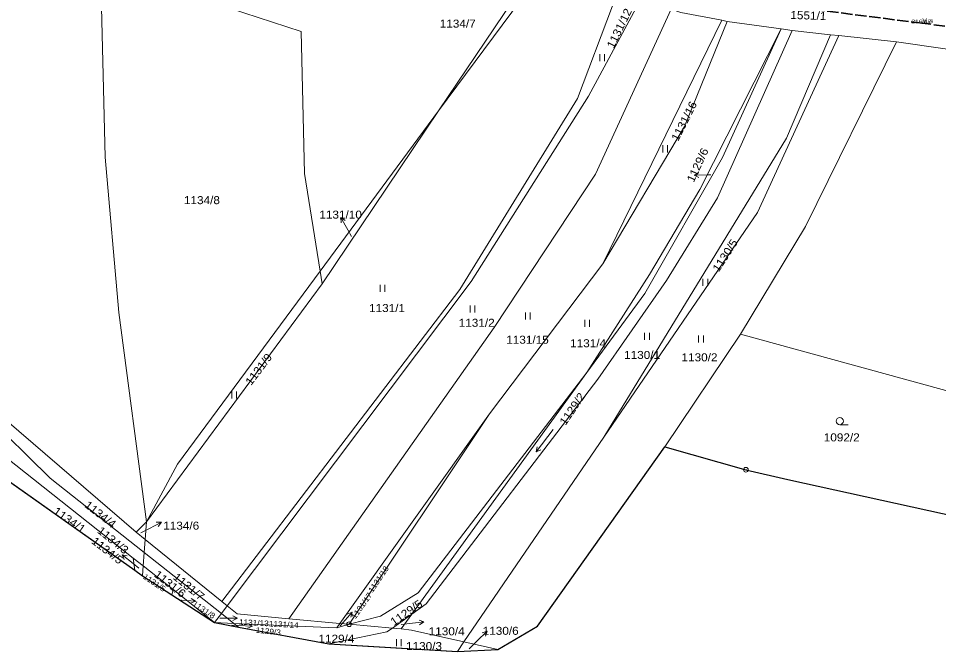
# Model space of a CAD drawing. Extents: x -686207 to -681951, y -1020493 to -1017811.
# Drawn here: x -684516.8 to -684321.3, y -1019707.1 to -1019572.5 of the extents above; entities that cross this region are included whole.
import ezdxf
from ezdxf.enums import TextEntityAlignment as Align

# ---------------------------------------------------------------- set-up
doc = ezdxf.new("R2010")
doc.units = 0
doc.header["$LTSCALE"] = 0.4
doc.header["$PDMODE"] = 32
doc.header["$PDSIZE"] = 0.2
doc.linetypes.add('LONG_DASHED', pattern=[7.5, 6, -1.5])
for name, color, linetype, lineweight in [('1', 7, 'Continuous', 13), ('24', 7, 'Continuous', 25), ('3', 7, 'Continuous', 13), ('35', 7, 'LONG_DASHED', 35), ('4', 7, 'Continuous', 13), ('7', 7, 'Continuous', 13), ('8', 7, 'Continuous', 13)]:
    doc.layers.add(name, color=color, linetype=linetype, lineweight=lineweight)
doc.layers.add('2', color=7, linetype='Continuous')

msp = doc.modelspace()

# ---------------------------------------------------------------- linework, layer by layer
at = {"layer": '1'}
for p, q in [((-684392.65, -1019624.67), (-684367.36, -1019572.95)), ((-684367.36, -1019572.95), (-684366.25, -1019573.17)), ((-684354.74, -1019574.74), (-684352.46, -1019575.08)), ((-684352.46, -1019575.08), (-684344.26, -1019576)), ((-684344.26, -1019576), (-684342.52, -1019576.2)), ((-684342.52, -1019576.2), (-684330.26, -1019577.49)), ((-684427.54, -1019592.19), (-684452.7, -1019626.22)), ((-684427.54, -1019592.19), (-684452.27, -1019628.92)), ((-684452.27, -1019628.92), (-684452.7, -1019626.22)), ((-684452.27, -1019628.92), (-684489.58, -1019679.5)), ((-684363.38, -1019639.61), (-684379.46, -1019663.55)), ((-684363.38, -1019639.61), (-684307.12, -1019655.1)), ((-684396.02, -1019647.8), (-684433.21, -1019699.09)), ((-684422.17, -1019705.03), (-684392.45, -1019661.53)), ((-684492.41, -1019687.22), (-684523.29, -1019662.77)), ((-684406.56, -1019701.65), (-684379.46, -1019663.55)), ((-684522.6, -1019668.21), (-684492.12, -1019689.8)), ((-684489.88, -1019683.27), (-684491.79, -1019681.72)), ((-684489.88, -1019683.27), (-684473.63, -1019696.41)), ((-684490.1, -1019686.01), (-684490.32, -1019688.88)), ((-684473.69, -1019698.98), (-684490.1, -1019686.01)), ((-684492.41, -1019687.22), (-684490.32, -1019688.88)), ((-684492.12, -1019689.8), (-684492.41, -1019687.22)), ((-684490.48, -1019690.96), (-684492.12, -1019689.8)), ((-684490.32, -1019688.88), (-684490.48, -1019690.96)), ((-684483.97, -1019693.9), (-684490.32, -1019688.88)), ((-684484.2, -1019695.03), (-684490.48, -1019690.96)), ((-684484.2, -1019695.03), (-684483.97, -1019693.9)), ((-684484.2, -1019695.03), (-684475.13, -1019700.9)), ((-684471.05, -1019701.07), (-684473.69, -1019698.98)), ((-684470.07, -1019701.85), (-684471.05, -1019701.07)), ((-684449.2, -1019702.01), (-684471.05, -1019701.07)), ((-684470.07, -1019701.85), (-684450.86, -1019705.44)), ((-684448.54, -1019701.08), (-684459.35, -1019700.09)), ((-684449.2, -1019702.01), (-684448.54, -1019701.08)), ((-684446.56, -1019701.26), (-684449.2, -1019702.01)), ((-684446.56, -1019701.26), (-684448.54, -1019701.08)), ((-684437.37, -1019702.07), (-684446.56, -1019701.26)), ((-684450.86, -1019705.44), (-684431.71, -1019706.58)), ((-684422.17, -1019705.03), (-684414.98, -1019706.64))]:
    msp.add_line(p, q, dxfattribs=at)
for points in [[(-684489.58, -1019679.5), (-684495.52, -1019635.01), (-684498.37, -1019602.06), (-684499.38, -1019561.4), (-684456.73, -1019575.36), (-684456.05, -1019605.49), (-684452.7, -1019626.22)], [(-684384.64, -1019568.56), (-684395.73, -1019589.06), (-684420.63, -1019628.47), (-684472.46, -1019697.35)], [(-684410.18, -1019568.72), (-684427.54, -1019592.19), (-684411.67, -1019568.63)], [(-684473.63, -1019696.41), (-684423.04, -1019630.15), (-684398.06, -1019589.57), (-684390.58, -1019569.88)], [(-684459.35, -1019700.09), (-684415.72, -1019638.24), (-684394.21, -1019605.65), (-684378.14, -1019570.61)], [(-684378.14, -1019570.61), (-684376.08, -1019571.26), (-684367.36, -1019572.95)], [(-684366.25, -1019573.17), (-684375.27, -1019595.48), (-684392.65, -1019624.67), (-684416.75, -1019656.53)], [(-684396.02, -1019647.8), (-684382.77, -1019626.93), (-684372.05, -1019608.93), (-684354.74, -1019574.74), (-684366.25, -1019573.17)], [(-684354.74, -1019574.74), (-684367.21, -1019602.1), (-684383.71, -1019630.97), (-684396.02, -1019647.8)], [(-684433.21, -1019699.09), (-684430.19, -1019696.93), (-684393.69, -1019649.17), (-684379.1, -1019628.23), (-684368.3, -1019610.64), (-684352.46, -1019575.08)], [(-684392.45, -1019661.53), (-684353.6, -1019598.02), (-684344.26, -1019576)], [(-684342.52, -1019576.2), (-684359.81, -1019613.76), (-684392.45, -1019661.53)], [(-684330.26, -1019577.49), (-684349.57, -1019616.78), (-684363.38, -1019639.61)], [(-684282.45, -1019625.86), (-684283.23, -1019624.61), (-684283.59, -1019589.07), (-684288.88, -1019583.44), (-684330.26, -1019577.49)], [(-684452.7, -1019626.22), (-684483.04, -1019667.25), (-684489.58, -1019679.5)], [(-684525.18, -1019647.91), (-684519.28, -1019658.03), (-684491.79, -1019681.72)], [(-684446.56, -1019701.26), (-684439.86, -1019699.56), (-684431.9, -1019694.61), (-684396.02, -1019647.8)], [(-684490.1, -1019686.01), (-684510.09, -1019670.21), (-684524.09, -1019656.5)], [(-684448.54, -1019701.08), (-684416.75, -1019656.53), (-684446.56, -1019701.26)], [(-684353.33, -1019670.49), (-684362.26, -1019668.43), (-684379.46, -1019663.55)], [(-684289.75, -1019683.18), (-684291.23, -1019682.83), (-684302.3, -1019681.04), (-684310.5, -1019679.94), (-684353.33, -1019670.49)], [(-684491.79, -1019681.72), (-684489.58, -1019679.5), (-684489.88, -1019683.27), (-684490.1, -1019686.01)], [(-684483.97, -1019693.9), (-684475.13, -1019700.9), (-684470.07, -1019701.85)], [(-684473.69, -1019698.98), (-684472.46, -1019697.35), (-684473.63, -1019696.41)], [(-684472.46, -1019697.35), (-684470.34, -1019699.07), (-684459.35, -1019700.09)], [(-684471.05, -1019701.07), (-684475.13, -1019700.9), (-684473.69, -1019698.98)], [(-684423.56, -1019707.07), (-684414.98, -1019706.64), (-684406.56, -1019701.65)], [(-684450.86, -1019705.44), (-684438.52, -1019702.9), (-684437.37, -1019702.07)], [(-684435.49, -1019702.24), (-684433.32, -1019702.54), (-684422.17, -1019705.03)], [(-684431.71, -1019706.58), (-684423.56, -1019707.07), (-684422.17, -1019705.03)]]:
    msp.add_lwpolyline(points, dxfattribs=at)
msp.add_lwpolyline([(-684435.49, -1019702.24), (-684437.37, -1019702.07), (-684433.21, -1019699.09)], close=True, dxfattribs=at)
msp.add_point((-684324.75, -1019573.56), dxfattribs=at)
at = {"layer": '24'}
msp.add_lwpolyline([(-684500.14, -1019451.56), (-684512.05, -1019478.99), (-684531.89, -1019512.67), (-684532.04, -1019515.06), (-684532.26, -1019518.47), (-684532.49, -1019522.07), (-684532.66, -1019524.82), (-684541.65, -1019550.12), (-684527.53, -1019664.73), (-684522.6, -1019668.21), (-684492.12, -1019689.8), (-684490.48, -1019690.96), (-684484.2, -1019695.03), (-684475.13, -1019700.9), (-684470.07, -1019701.85), (-684450.86, -1019705.44), (-684423.56, -1019707.07), (-684414.98, -1019706.64), (-684406.56, -1019701.65), (-684379.46, -1019663.55), (-684362.26, -1019668.43), (-684353.33, -1019670.49), (-684310.5, -1019679.94)], dxfattribs=at)
at = {"layer": '3'}
for p, q in [((-684393.311, -1019581.63), (-684393.311, -1019580.13)), ((-684392.31, -1019581.63), (-684392.31, -1019580.13)), ((-684379.921, -1019601.01), (-684379.921, -1019599.51)), ((-684378.92, -1019601.01), (-684378.92, -1019599.51)), ((-684439.991, -1019630.63), (-684439.991, -1019629.13)), ((-684438.99, -1019630.63), (-684438.99, -1019629.13)), ((-684371.381, -1019629.36), (-684371.381, -1019627.86)), ((-684370.38, -1019629.36), (-684370.38, -1019627.86)), ((-684420.831, -1019635.01), (-684420.831, -1019633.51)), ((-684419.83, -1019635.01), (-684419.83, -1019633.51)), ((-684409.061, -1019636.53), (-684409.061, -1019635.03)), ((-684408.06, -1019636.53), (-684408.06, -1019635.03)), ((-684396.491, -1019638.1), (-684396.491, -1019636.6)), ((-684395.49, -1019638.1), (-684395.49, -1019636.6)), ((-684383.771, -1019640.84), (-684383.771, -1019639.34)), ((-684382.77, -1019640.84), (-684382.77, -1019639.34)), ((-684372.301, -1019641.42), (-684372.301, -1019639.92)), ((-684371.3, -1019641.42), (-684371.3, -1019639.92)), ((-684471.481, -1019653.33), (-684471.481, -1019651.83)), ((-684470.48, -1019653.33), (-684470.48, -1019651.83)), ((-684342.303, -1019658.86), (-684340.553, -1019658.86)), ((-684406.793, -1019664.664), (-684406.605, -1019663.582)), ((-684436.481, -1019705.9), (-684436.481, -1019704.4)), ((-684435.48, -1019705.9), (-684435.48, -1019704.4))]:
    msp.add_line(p, q, dxfattribs=at)
msp.add_lwpolyline([(-684403.182, -1019659.873), (-684406.793, -1019664.664), (-684405.804, -1019664.186)], dxfattribs=at)
msp.add_circle((-684342.3029, -1019658.1098), 0.75, dxfattribs=at)
at = {"layer": '35'}
msp.add_lwpolyline([(-684314.027, -1019574.999), (-684324.75, -1019573.56), (-684347.24, -1019570.74), (-684348.992, -1019570.517)], dxfattribs=at)
at = {"layer": '7'}
for p, q in [((-684373.249, -1019605.875), (-684372.231, -1019606.34)), ((-684448.295, -1019614.845), (-684448.247, -1019615.964)), ((-684446.07, -1019618.86), (-684446.84, -1019617.47)), ((-684486.45, -1019679.551), (-684487.57, -1019679.579)), ((-684494.805, -1019686.522), (-684494.324, -1019687.534)), ((-684479.19, -1019696.372), (-684480.144, -1019695.785)), ((-684482.18, -1019696.11), (-684482.22, -1019696.11)), ((-684470.269, -1019699.938), (-684471.28, -1019699.454)), ((-684445.912, -1019698.71), (-684446.954, -1019699.119)), ((-684467.123, -1019701.667), (-684468.097, -1019701.115)), ((-684430.655, -1019700.776), (-684431.704, -1019700.383)), ((-684417.231, -1019702.755), (-684418.3, -1019703.091)), ((-684421.05, -1019706.45), (-684419.39, -1019704.84))]:
    msp.add_line(p, q, dxfattribs=at)
for points in [[(-684369.69, -1019605.75), (-684370.25, -1019605.77), (-684373.249, -1019605.875), (-684372.266, -1019605.339)], [(-684446.84, -1019617.47), (-684448.295, -1019614.845), (-684447.371, -1019615.478)], [(-684490.8, -1019681.86), (-684489.1, -1019680.96), (-684486.45, -1019679.551), (-684487.099, -1019680.463)], [(-684491.23, -1019689.33), (-684492.44, -1019688.37), (-684494.805, -1019686.522), (-684493.707, -1019686.744)], [(-684482.18, -1019696.11), (-684479.19, -1019696.372), (-684480.232, -1019696.783)], [(-684448.49, -1019701.57), (-684447.92, -1019700.94), (-684445.912, -1019698.71), (-684446.21, -1019699.789)], [(-684474.01, -1019700), (-684473.27, -1019699.99), (-684470.269, -1019699.938), (-684471.262, -1019700.456)], [(-684471.49, -1019701.43), (-684470.12, -1019701.51), (-684467.123, -1019701.667), (-684468.149, -1019702.115)], [(-684435.47, -1019701.28), (-684433.64, -1019701.09), (-684430.655, -1019700.776), (-684431.599, -1019701.379)], [(-684419.39, -1019704.84), (-684417.231, -1019702.755), (-684417.604, -1019703.811)]]:
    msp.add_lwpolyline(points, dxfattribs=at)
at = {"layer": '8'}
for centre, radius in [((-684362.26, -1019668.4299), 0.5), ((-684362.26, -1019668.4299), 0.0303), ((-684446.56, -1019701.2599), 0.5), ((-684446.56, -1019701.2599), 0.0303)]:
    msp.add_circle(centre, radius, dxfattribs=at)

# ---------------------------------------------------------------- texts
at = {"layer": '2', "width": 1.1}
for s, height, rotation, p in [('1131/12', 1.7, 64, (-684390.376, -1019579.082)), ('1551/1', 1.7, 358, (-684352.833, -1019572.644)), ('1131/16', 1.7, 63, (-684376.682, -1019598.775)), ('1129/6', 1.7, 65, (-684373.362, -1019607.527)), ('1130/5', 1.7, 57, (-684368.057, -1019626.572)), ('1131/9', 1.7, 53, (-684467.391, -1019650.651)), ('1129/2', 1.7, 56, (-684400.585, -1019659.145)), ('1134/4', 1.7, 322, (-684502.933, -1019676.219)), ('1134/1', 1.7, 325, (-684509.587, -1019677.606)), ('1134/3', 1.7, 321, (-684500.224, -1019681.67)), ('1134/5', 1.7, 322, (-684501.454, -1019683.912)), ('1131/6', 1.7, 322, (-684488.143, -1019690.999)), ('1131/18', 1.19, 56, (-684441.586, -1019694.642)), ('1131/5', 1.19, 326, (-684490.482, -1019691.443)), ('1131/7', 1.7, 321, (-684484.124, -1019691.52)), ('1131/17', 1.19, 55, (-684445.217, -1019700.259)), ('1131/8', 1.19, 326, (-684479.959, -1019697.175)), ('1129/5', 1.7, 35, (-684437.052, -1019701.686)), ('1131/13', 1.19, 357, (-684469.991, -1019701.354)), ('1131/14', 1.19, 357, (-684463.631, -1019701.714)), ('1129/3', 1.19, 354, (-684466.462, -1019703.051))]:
    msp.add_text(s, height=height, rotation=rotation, dxfattribs=at).set_placement(p)
for s, p in [('1134/7', (-684427.311, -1019574.503)), ('1134/8', (-684481.66, -1019612.01)), ('1131/10', (-684452.886, -1019615.08)), ('1131/1', (-684442.33, -1019634.929)), ('1131/2', (-684423.28, -1019638.059)), ('1131/15', (-684413.18, -1019641.66)), ('1131/4', (-684399.61, -1019642.41)), ('1130/1', (-684388.14, -1019644.89)), ('1130/2', (-684375.94, -1019645.4)), ('1092/2', (-684345.715, -1019662.41)), ('1134/6', (-684486.06, -1019681.163)), ('1130/4', (-684429.66, -1019703.613)), ('1130/6', (-684418.181, -1019703.503)), ('1129/4', (-684453.08, -1019705.179)), ('1130/3', (-684434.47, -1019706.75))]:
    msp.add_text(s, height=1.7, dxfattribs=at).set_placement(p)
at = {"layer": '2'}
msp.add_text('0159', height=0.75, dxfattribs=at).set_placement((-684324.75, -1019573.56))
at = {"layer": '3', "width": 1.4}
msp.add_text('216 17 ', height=0.75, dxfattribs=at).set_placement((-684324.75, -1019573.56), align=Align.CENTER)
at = {"layer": '4', "width": 0.85}
msp.add_text('V', height=1, dxfattribs=at).set_placement((-684324.75, -1019573.56))

doc.saveas('drawing.dxf')
